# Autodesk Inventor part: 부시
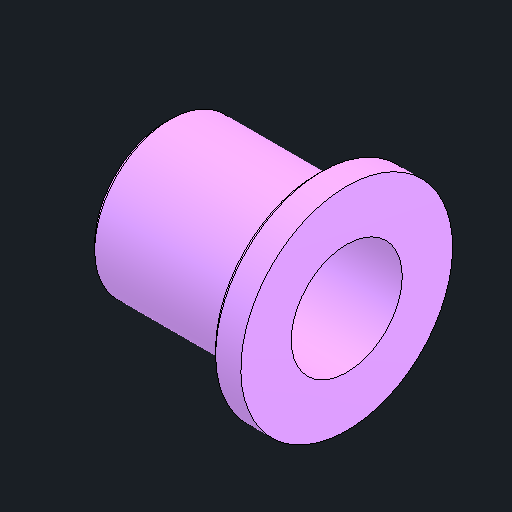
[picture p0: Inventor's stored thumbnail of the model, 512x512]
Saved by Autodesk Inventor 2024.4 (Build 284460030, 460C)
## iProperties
Created: 2026-08
Part Number: 부시
Material: 강철, 연강
Document SubType Name: Modeling
Designer: user
Density: 7.86 g/cm^3
Appearance: 기본값
Author: jhkim
Sending System: Autodesk Inventor 2027
Preprocessor: ST-DEVELOPER v20.1
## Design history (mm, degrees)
feature "솔리드1"
node "솔리드2"
